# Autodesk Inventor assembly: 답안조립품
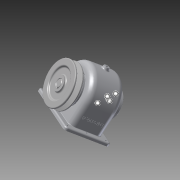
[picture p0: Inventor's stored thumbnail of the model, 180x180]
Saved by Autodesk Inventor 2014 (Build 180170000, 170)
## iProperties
Created: 2015-09
Part Number: 답안조립품
Document SubType Name: Assembly
Designer: SEC
Author: SEC
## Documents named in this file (10)
- C:\Users\SEC\Desktop\450907V1017\답안조립품.iam
- C:\Users\SEC\Desktop\450907V1017\본체.ipt
- C:\Users\SEC\Desktop\450907V1017\앞커버.ipt
- C:\Users\SEC\Desktop\450907V1017\베어링 6203.ipt
- C:\Users\SEC\Desktop\450907V1017\축.ipt
- C:\Users\SEC\Desktop\450907V1017\뒤커버.ipt
- C:\Users\SEC\Desktop\450907V1017\V-벨트풀리.ipt
- C:\Users\SEC\Desktop\450907V1017\스퍼기어.ipt
- C:\Users\SEC\Desktop\450907V1017\볼트 M3 x 8.ipt
- C:\Users\SEC\Desktop\450907V1017\볼트 M3 x 10.ipt
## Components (9 placed, 3 different names)
1. V-벨트풀리:1
2. ISO 4762 M3 x 8:5
3. ISO 4762 M3 x 8:6
4. ISO 4762 M3 x 8:7
5. ISO 4762 M3 x 8:8
6. ISO 4762 M3 x 10:1
7. ISO 4762 M3 x 10:2
8. ISO 4762 M3 x 10:3
9. ISO 4762 M3 x 10:4
